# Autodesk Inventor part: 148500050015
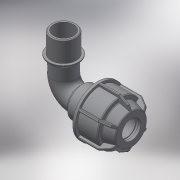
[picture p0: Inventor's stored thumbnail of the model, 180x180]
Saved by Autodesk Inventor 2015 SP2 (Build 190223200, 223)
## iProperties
Created: 2017-08
Part Number: 148500050015
Material: Generic
Description: PLASSON L.14 90° ELBOW MALE ADAPTOR (SILVER) 50-1.1/2"
Document SubType Name: Modeling
Designer: KIM
Density: 1 g/cm^3
Appearance: Default
Author: KIM
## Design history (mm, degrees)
derived "148500.ipt"
feature "Solid1::148500.ipt"
feature "Solid2::148500.ipt"
tag "TaggingFeature1"
body "Solid1"
body "Solid2"
other parameters: "d2" = 74, "d4" = 15 deg, "d5" = 48.84, "d6" = 16.1172, "d10" = 92, "d16" = 51, "d17" = 3.7, "d24" = 3.7, "d25" = 82.8, "d26" = 69, "d27" = 3.7, "d28" = 135 deg, "d29" = 2.22, "d31" = 2.5, "d46" = 150 deg, "d49" = 4.6, "d50" = 0, "d58" = 1.5, "d61" = 360 deg, "d94" = 73, "d96" = 52.5833, "d97" = 22, "d98" = 38.2424, "d99" = 44.69581, "d100" = 135 deg, "d108" = 2.5, "d112" = 28.6, "d113" = 104, "d114" = 82.88, "d115" = 44.69581, "d116" = 45 deg, "d117" = 0, "d118" = 0, "d119" = 47.803, "d120" = 22, "d121" = 57.3636, "d122" = 23.1, "d123" = 1, "R_" = 47.803, "E_" = 92, "A_" = 104, "l_" = 74, "l_2" = 22, "A_1" = 73
